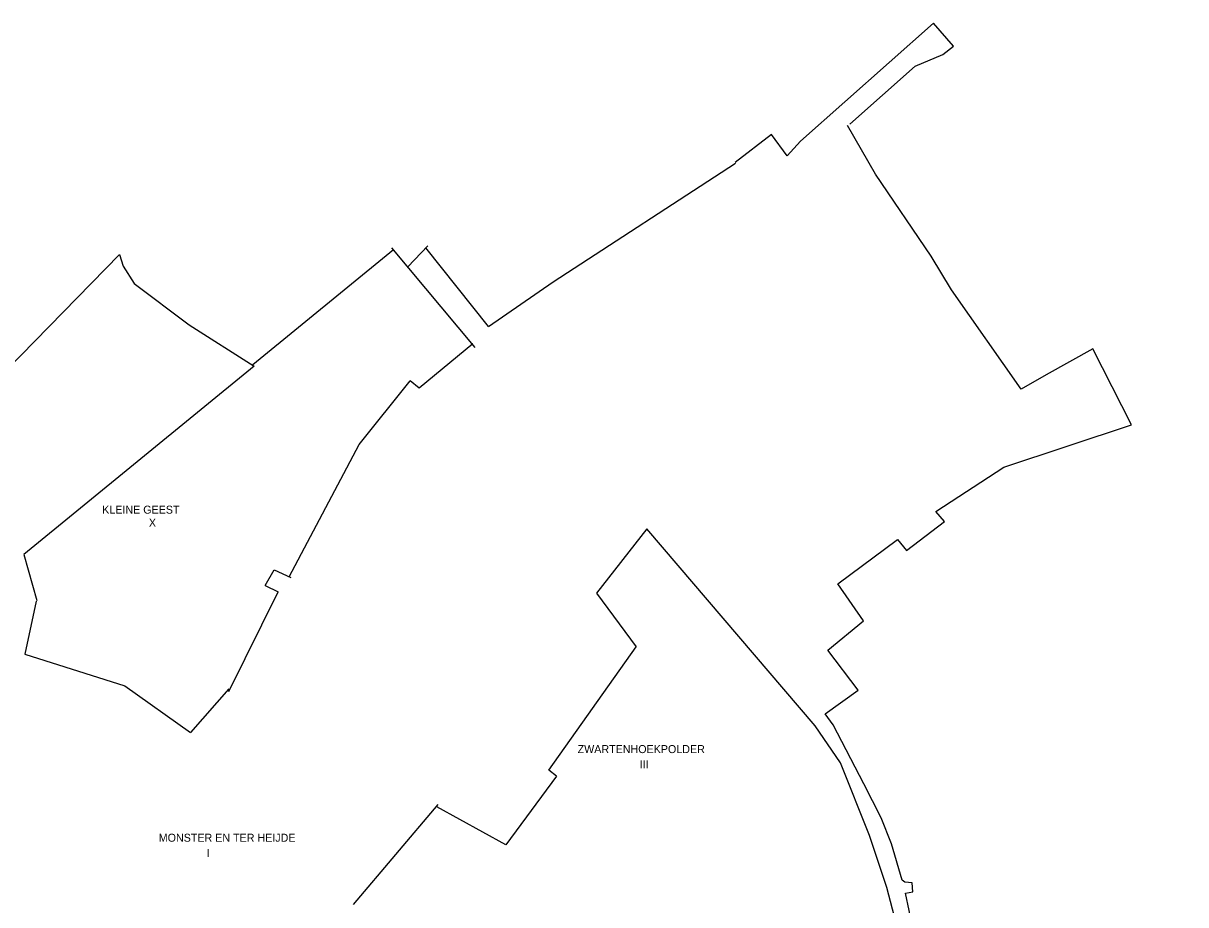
# Model space of a CAD drawing. Extents: x 69068 to 80855, y 440023 to 451362.
# Drawn here: x 71365 to 72673, y 449305 to 450297 of the extents above; entities that cross this region are included whole.
import ezdxf

# ---------------------------------------------------------------- set-up
doc = ezdxf.new("R2010")
doc.units = 0
for name, color, linetype in [('Bemalingsgebiedsgrens', 7, 'Continuous'), ('Bemalingsgebiedsnummer', 7, 'Continuous'), ('RIO_Leidingen', 7, 'Continuous')]:
    doc.layers.add(name, color=color, linetype=linetype)

msp = doc.modelspace()

# ---------------------------------------------------------------- linework, layer by layer
at = {"layer": 'Bemalingsgebiedsgrens'}
for p, q in [((71961.4, 450006.1), (72166.7, 450139.6)), ((71961.4, 450006.1), (72166.7, 450139.6)), ((71961.4, 450006.1), (72166.7, 450139.6)), ((71961.4, 450006.1), (72166.7, 450139.6)), ((71820.4, 450046.7), (71797.9, 450023)), ((71820.4, 450046.7), (71797.9, 450023)), ((71820.4, 450046.7), (71797.9, 450023)), ((71820.4, 450046.7), (71797.9, 450023)), ((71888.7, 449955.7), (71961.4, 450006.1)), ((71888.7, 449955.7), (71961.4, 450006.1)), ((71888.7, 449955.7), (71961.4, 450006.1)), ((71888.7, 449955.7), (71961.4, 450006.1)), ((71743.3, 449823.2), (71800.7, 449894.7)), ((71743.3, 449823.2), (71800.7, 449894.7)), ((71743.3, 449823.2), (71800.7, 449894.7)), ((71743.3, 449823.2), (71800.7, 449894.7)), ((71664.6, 449674.3), (71743.3, 449823.2)), ((71664.6, 449674.3), (71743.3, 449823.2)), ((71664.6, 449674.3), (71743.3, 449823.2)), ((71664.6, 449674.3), (71743.3, 449823.2)), ((72066.8, 449728.4), (72010.1, 449655.7)), ((72066.8, 449728.4), (72010.1, 449655.7)), ((72066.8, 449728.4), (72010.1, 449655.7)), ((72066.8, 449728.4), (72010.1, 449655.7)), ((72256.2, 449506.7), (72066.8, 449728.4)), ((72256.2, 449506.7), (72066.8, 449728.4)), ((72256.2, 449506.7), (72066.8, 449728.4)), ((72256.2, 449506.7), (72066.8, 449728.4)), ((71637.5, 449664.6), (71647.6, 449682.3)), ((71637.5, 449664.6), (71647.6, 449682.3)), ((71637.5, 449664.6), (71647.6, 449682.3)), ((71637.5, 449664.6), (71647.6, 449682.3)), ((71647.6, 449682.3), (71666.3, 449673.5)), ((71647.6, 449682.3), (71666.3, 449673.5)), ((71647.6, 449682.3), (71666.3, 449673.5)), ((71647.6, 449682.3), (71666.3, 449673.5)), ((71596.6, 449545.4), (71652.2, 449657.5)), ((71596.6, 449545.4), (71652.2, 449657.5)), ((71596.6, 449545.4), (71652.2, 449657.5)), ((71596.6, 449545.4), (71652.2, 449657.5)), ((71637.5, 449664.6), (71652.2, 449657.5)), ((71637.5, 449664.6), (71652.2, 449657.5)), ((71637.5, 449664.6), (71652.2, 449657.5)), ((71637.5, 449664.6), (71652.2, 449657.5)), ((71379.9, 449646.8), (71367.4, 449587.2)), ((71379.9, 449646.8), (71367.4, 449587.2)), ((71379.9, 449646.8), (71367.4, 449587.2)), ((71379.9, 449646.8), (71367.4, 449587.2)), ((72010.1, 449655.7), (72054.8, 449595.4)), ((72010.1, 449655.7), (72054.8, 449595.4)), ((72010.1, 449655.7), (72054.8, 449595.4)), ((72010.1, 449655.7), (72054.8, 449595.4)), ((71367.4, 449587.2), (71479.6, 449551.5)), ((71367.4, 449587.2), (71479.6, 449551.5)), ((71367.4, 449587.2), (71479.6, 449551.5)), ((71367.4, 449587.2), (71479.6, 449551.5)), ((71479.6, 449551.5), (71553.7, 449499.2)), ((71479.6, 449551.5), (71553.7, 449499.2)), ((71479.6, 449551.5), (71553.7, 449499.2)), ((71479.6, 449551.5), (71553.7, 449499.2)), ((71596.9, 449548.4), (71553.7, 449499.2)), ((71596.9, 449548.4), (71553.7, 449499.2)), ((71596.9, 449548.4), (71553.7, 449499.2)), ((71596.9, 449548.4), (71553.7, 449499.2)), ((72284.5, 449465), (72256.2, 449506.7)), ((72284.5, 449465), (72256.2, 449506.7)), ((72284.5, 449465), (72256.2, 449506.7)), ((72284.5, 449465), (72256.2, 449506.7)), ((72317.3, 449383.2), (72284.5, 449465)), ((72317.3, 449383.2), (72284.5, 449465)), ((72317.3, 449383.2), (72284.5, 449465)), ((72317.3, 449383.2), (72284.5, 449465)), ((71965.1, 449450.1), (71908.2, 449372.9)), ((71965.1, 449450.1), (71908.2, 449372.9)), ((71965.1, 449450.1), (71908.2, 449372.9)), ((71965.1, 449450.1), (71908.2, 449372.9)), ((71831.7, 449418.2), (71736.6, 449305.8)), ((71831.7, 449418.2), (71736.6, 449305.8)), ((71831.7, 449418.2), (71736.6, 449305.8)), ((71831.7, 449418.2), (71736.6, 449305.8)), ((71908.2, 449372.9), (71830.7, 449415.5)), ((71908.2, 449372.9), (71830.7, 449415.5)), ((71908.2, 449372.9), (71830.7, 449415.5)), ((71908.2, 449372.9), (71830.7, 449415.5)), ((72336.6, 449324.8), (72317.3, 449383.2)), ((72336.6, 449324.8), (72317.3, 449383.2)), ((72336.6, 449324.8), (72317.3, 449383.2)), ((72336.6, 449324.8), (72317.3, 449383.2)), ((72362.6, 449228.3), (72336.6, 449324.8)), ((72362.6, 449228.3), (72336.6, 449324.8)), ((72362.6, 449228.3), (72336.6, 449324.8)), ((72362.6, 449228.3), (72336.6, 449324.8))]:
    msp.add_line(p, q, dxfattribs=at)
for points in [[(72295.2, 450183.5), (72368.5, 450248.6), (72399.7, 450261.7), (72411.9, 450271.3), (72389.2, 450296.9), (72239.7, 450164.3), (72224.8, 450147.7), (72207.2, 450171.9), (72166.1, 450140.5)], [(72295.2, 450183.5), (72368.5, 450248.6), (72399.7, 450261.7), (72411.9, 450271.3), (72389.2, 450296.9), (72239.7, 450164.3), (72224.8, 450147.7), (72207.2, 450171.9), (72166.1, 450140.5)], [(72295.2, 450183.5), (72368.5, 450248.6), (72399.7, 450261.7), (72411.9, 450271.3), (72389.2, 450296.9), (72239.7, 450164.3), (72224.8, 450147.7), (72207.2, 450171.9), (72166.1, 450140.5)], [(72295.2, 450183.5), (72368.5, 450248.6), (72399.7, 450261.7), (72411.9, 450271.3), (72389.2, 450296.9), (72239.7, 450164.3), (72224.8, 450147.7), (72207.2, 450171.9), (72166.1, 450140.5)], [(72357.7, 449318.6), (72365.9, 449319.9), (72365.1, 449329.9), (72357.2, 449330.9), (72353.9, 449333.2), (72341.9, 449374), (72330.3, 449403.2), (72311.1, 449441.6), (72276.3, 449507.9), (72267.5, 449520.2), (72304.5, 449546.9), (72270.6, 449591.8), (72310.4, 449624.9), (72281.8, 449666.2), (72348.8, 449716.2), (72358.9, 449703.9), (72401.7, 449736.5), (72392, 449747.6), (72468.5, 449797.7), (72612.1, 449845.3), (72568.6, 449930.9), (72516.1, 449901.5), (72487.7, 449885.4), (72409.6, 449997.2), (72386.5, 450034.8), (72324, 450127.1), (72292.4, 450182.1)], [(72357.7, 449318.6), (72365.9, 449319.9), (72365.1, 449329.9), (72357.2, 449330.9), (72353.9, 449333.2), (72341.9, 449374), (72330.3, 449403.2), (72311.1, 449441.6), (72276.3, 449507.9), (72267.5, 449520.2), (72304.5, 449546.9), (72270.6, 449591.8), (72310.4, 449624.9), (72281.8, 449666.2), (72348.8, 449716.2), (72358.9, 449703.9), (72401.7, 449736.5), (72392, 449747.6), (72468.5, 449797.7), (72612.1, 449845.3), (72568.6, 449930.9), (72516.1, 449901.5), (72487.7, 449885.4), (72409.6, 449997.2), (72386.5, 450034.8), (72324, 450127.1), (72292.4, 450182.1)], [(72357.7, 449318.6), (72365.9, 449319.9), (72365.1, 449329.9), (72357.2, 449330.9), (72353.9, 449333.2), (72341.9, 449374), (72330.3, 449403.2), (72311.1, 449441.6), (72276.3, 449507.9), (72267.5, 449520.2), (72304.5, 449546.9), (72270.6, 449591.8), (72310.4, 449624.9), (72281.8, 449666.2), (72348.8, 449716.2), (72358.9, 449703.9), (72401.7, 449736.5), (72392, 449747.6), (72468.5, 449797.7), (72612.1, 449845.3), (72568.6, 449930.9), (72516.1, 449901.5), (72487.7, 449885.4), (72409.6, 449997.2), (72386.5, 450034.8), (72324, 450127.1), (72292.4, 450182.1)], [(72357.7, 449318.6), (72365.9, 449319.9), (72365.1, 449329.9), (72357.2, 449330.9), (72353.9, 449333.2), (72341.9, 449374), (72330.3, 449403.2), (72311.1, 449441.6), (72276.3, 449507.9), (72267.5, 449520.2), (72304.5, 449546.9), (72270.6, 449591.8), (72310.4, 449624.9), (72281.8, 449666.2), (72348.8, 449716.2), (72358.9, 449703.9), (72401.7, 449736.5), (72392, 449747.6), (72468.5, 449797.7), (72612.1, 449845.3), (72568.6, 449930.9), (72516.1, 449901.5), (72487.7, 449885.4), (72409.6, 449997.2), (72386.5, 450034.8), (72324, 450127.1), (72292.4, 450182.1)], [(71473.7, 450037), (71314.7, 449874.3), (71289.7, 449856.5), (71183.6, 449736.4), (71162.7, 449713.8)], [(71473.7, 450037), (71314.7, 449874.3), (71289.7, 449856.5), (71183.6, 449736.4), (71162.7, 449713.8)], [(71473.7, 450037), (71314.7, 449874.3), (71289.7, 449856.5), (71183.6, 449736.4), (71162.7, 449713.8)], [(71473.7, 450037), (71314.7, 449874.3), (71289.7, 449856.5), (71183.6, 449736.4), (71162.7, 449713.8)], [(71473.7, 450037), (71473.7, 450037), (71477.9, 450023.6), (71490.1, 450004.1), (71552.1, 449957.6), (71625.4, 449911.2), (71366.3, 449699.3), (71380.6, 449647.5)], [(71473.7, 450037), (71473.7, 450037), (71477.9, 450023.6), (71490.1, 450004.1), (71552.1, 449957.6), (71625.4, 449911.2), (71366.3, 449699.3), (71380.6, 449647.5)], [(71473.7, 450037), (71473.7, 450037), (71477.9, 450023.6), (71490.1, 450004.1), (71552.1, 449957.6), (71625.4, 449911.2), (71366.3, 449699.3), (71380.6, 449647.5)], [(71473.7, 450037), (71473.7, 450037), (71477.9, 450023.6), (71490.1, 450004.1), (71552.1, 449957.6), (71625.4, 449911.2), (71366.3, 449699.3), (71380.6, 449647.5)], [(71782.1, 450042.1), (71623.6, 449912.9)], [(71782.1, 450042.1), (71623.6, 449912.9)], [(71782.1, 450042.1), (71623.6, 449912.9)], [(71782.1, 450042.1), (71623.6, 449912.9)], [(71873.7, 449932.1), (71780.2, 450044.4)], [(71873.7, 449932.1), (71780.2, 450044.4)], [(71873.7, 449932.1), (71780.2, 450044.4)], [(71873.7, 449932.1), (71780.2, 450044.4)], [(71888.7, 449955.7), (71818.4, 450044.2)], [(71888.7, 449955.7), (71818.4, 450044.2)], [(71888.7, 449955.7), (71818.4, 450044.2)], [(71888.7, 449955.7), (71818.4, 450044.2)], [(71871.2, 449936.2), (71810.7, 449886.5), (71800.7, 449894.7)], [(71871.2, 449936.2), (71810.7, 449886.5), (71800.7, 449894.7)], [(71871.2, 449936.2), (71810.7, 449886.5), (71800.7, 449894.7)], [(71871.2, 449936.2), (71810.7, 449886.5), (71800.7, 449894.7)], [(71965.1, 449450.1), (71956.8, 449456.8), (72054.8, 449595.4)], [(71965.1, 449450.1), (71956.8, 449456.8), (72054.8, 449595.4)], [(71965.1, 449450.1), (71956.8, 449456.8), (72054.8, 449595.4)], [(71965.1, 449450.1), (71956.8, 449456.8), (72054.8, 449595.4)], [(73113.5, 448972.1), (72993.5, 448964.8), (72895.4, 448937.3), (72837.5, 448929.9), (72667.2, 448904.2), (72502.7, 448886.9), (72500.3, 448906.4), (72481.2, 448903.2), (72474.7, 448933.7), (72466, 448983.7), (72463.3, 449028.9), (72430.3, 449116.2), (72394.4, 449192.2), (72374.1, 449240.4), (72357.7, 449318.6)], [(73113.5, 448972.1), (72993.5, 448964.8), (72895.4, 448937.3), (72837.5, 448929.9), (72667.2, 448904.2), (72502.7, 448886.9), (72500.3, 448906.4), (72481.2, 448903.2), (72474.7, 448933.7), (72466, 448983.7), (72463.3, 449028.9), (72430.3, 449116.2), (72394.4, 449192.2), (72374.1, 449240.4), (72357.7, 449318.6)], [(73113.5, 448972.1), (72993.5, 448964.8), (72895.4, 448937.3), (72837.5, 448929.9), (72667.2, 448904.2), (72502.7, 448886.9), (72500.3, 448906.4), (72481.2, 448903.2), (72474.7, 448933.7), (72466, 448983.7), (72463.3, 449028.9), (72430.3, 449116.2), (72394.4, 449192.2), (72374.1, 449240.4), (72357.7, 449318.6)], [(73113.5, 448972.1), (72993.5, 448964.8), (72895.4, 448937.3), (72837.5, 448929.9), (72667.2, 448904.2), (72502.7, 448886.9), (72500.3, 448906.4), (72481.2, 448903.2), (72474.7, 448933.7), (72466, 448983.7), (72463.3, 449028.9), (72430.3, 449116.2), (72394.4, 449192.2), (72374.1, 449240.4), (72357.7, 449318.6)]]:
    msp.add_lwpolyline(points, dxfattribs=at)

# ---------------------------------------------------------------- texts
at = {"layer": 'Bemalingsgebiedsnummer'}
for s, p in [('X', (71506.8, 449730.7)), ('X', (71506.8, 449730.7)), ('X', (71506.8, 449730.7)), ('X', (71506.8, 449730.7)), ('III', (72058.7, 449458.8)), ('III', (72058.7, 449458.8)), ('III', (72058.7, 449458.8)), ('III', (72058.7, 449458.8)), (' I', (71568.6, 449359.1)), (' I', (71568.6, 449359.1)), (' I', (71568.6, 449359.1)), (' I', (71568.6, 449359.1))]:
    msp.add_text(s, height=9, dxfattribs=at).set_placement(p)
at = {"layer": 'RIO_Leidingen'}
for s, p in [('KLEINE GEEST', (71454.3, 449745.3)), ('KLEINE GEEST', (71454.3, 449745.3)), ('KLEINE GEEST', (71454.3, 449745.3)), ('KLEINE GEEST', (71454.3, 449745.3)), ('ZWARTENHOEKPOLDER', (71989, 449476)), ('ZWARTENHOEKPOLDER', (71989, 449476)), ('ZWARTENHOEKPOLDER', (71989, 449476)), ('ZWARTENHOEKPOLDER', (71989, 449476)), ('MONSTER EN TER HEIJDE', (71517.9, 449376.3)), ('MONSTER EN TER HEIJDE', (71517.9, 449376.3)), ('MONSTER EN TER HEIJDE', (71517.9, 449376.3)), ('MONSTER EN TER HEIJDE', (71517.9, 449376.3))]:
    msp.add_text(s, height=9, dxfattribs=at).set_placement(p)

doc.saveas('drawing.dxf')
